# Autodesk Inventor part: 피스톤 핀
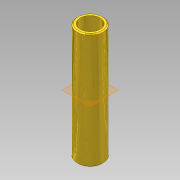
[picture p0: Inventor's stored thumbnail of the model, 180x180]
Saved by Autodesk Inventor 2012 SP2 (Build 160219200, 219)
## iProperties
Manager: KYOUNG IL JANG
Company: 한국ATC센터
Created: 2012-10
Part Number: 피스톤 핀
Document SubType Name: Modeling
Density: 1 g/cm^3
Checked By: KYOUNG IL JANG
Vendor: CBT Solutions
Designer: KYOUNG IL JANG
Material: 기본값
Author: KYOUNG IL JANG
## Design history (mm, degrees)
sketch "스케치1"
  geometry: C1 r 6.5 at (0, 0); C2 r 5 at (0, 0); 1 further point
  constraints: 2 centre point, 2 coincident
  dimensions: "d0" = 13 diameter of C1; "d1" = 1.5 radial gap between concentric circles of C1 C2
extrude "돌출1" new body sketch "스케치1" stored distance "d2" = 58; taper "d3" = 0 deg
chamfer "모따기1" distance "d4" = 0.5; stored, may be unused: second distance "d5" = 2, angle "d6" = 45 deg
node "솔리드1"
